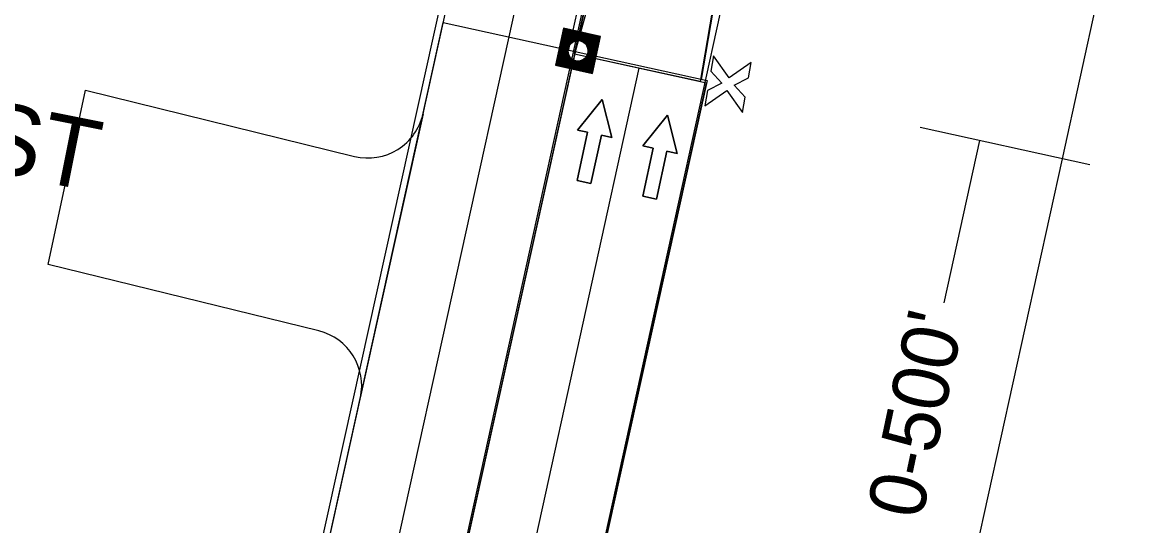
# Model space of a CAD drawing. Extents: x 14104283 to 14121738, y 8635219 to 8671666.
# Drawn here: x 14107527.6 to 14107724.8, y 8638157 to 8638246.4 of the extents above; entities that cross this region are included whole.
import ezdxf

# ---------------------------------------------------------------- set-up
doc = ezdxf.new("R2010")
doc.units = 0
for name, color, linetype in [('Cell', 7, 'Continuous'), ('Default', 7, 'Continuous'), ('dsnCellElements', 7, 'Continuous'), ('dsnNonPlotable', 7, 'Continuous'), ('dsnPaintExistingBrokenLaneLineWhite', 7, 'Continuous'), ('dsnPaintExistingDoubleCenterYellow', 7, 'Continuous'), ('dsnPaintExistingEdgeLineRightWhite', 7, 'Continuous'), ('dsnStdLabel', 7, 'Continuous'), ('dsnTapePlaceChannelizingLaneWhite', 7, 'Continuous'), ('dsnTapeRemoveChannelizingYellow', 7, 'Continuous'), ('dsnTextOverlapOdd', 7, 'Continuous')]:
    doc.layers.add(name, color=color, linetype=linetype)

msp = doc.modelspace()

# ---------------------------------------------------------------- linework, layer by layer
at = {"layer": 'Cell'}
for p, q in [((14107650.37, 8638240.4), (14107649.9, 8638237.69)), ((14107653.12, 8638236.5), (14107650.37, 8638240.4)), ((14107657.02, 8638239.24), (14107653.12, 8638236.5)), ((14107656.55, 8638236.53), (14107657.02, 8638239.24)), ((14107649.9, 8638237.69), (14107651.82, 8638235.58)), ((14107654.03, 8638235.19), (14107656.55, 8638236.53)), ((14107648.83, 8638231.54), (14107652.73, 8638234.28)), ((14107649.3, 8638234.24), (14107648.83, 8638231.54)), ((14107651.82, 8638235.58), (14107649.3, 8638234.24)), ((14107652.73, 8638234.28), (14107655.47, 8638230.37)), ((14107655.95, 8638233.08), (14107654.03, 8638235.19)), ((14107655.47, 8638230.37), (14107655.95, 8638233.08))]:
    msp.add_line(p, q, dxfattribs=at)
for points in [[(14107628.58, 8638217.76), (14107626.13, 8638218.29), (14107628, 8638226.84), (14107626.17, 8638227.24), (14107630.55, 8638232.68), (14107632.27, 8638225.91), (14107630.44, 8638226.31)], [(14107640.21, 8638214.94), (14107637.77, 8638215.47), (14107639.63, 8638224.02), (14107637.8, 8638224.42), (14107642.19, 8638229.86), (14107643.91, 8638223.09), (14107642.08, 8638223.49)]]:
    msp.add_lwpolyline(points, close=True, dxfattribs=at)
for points in [[(14107630.44, 8638226.31), (14107632.27, 8638225.91), (14107630.55, 8638232.68), (14107626.17, 8638227.24), (14107628, 8638226.84), (14107626.13, 8638218.29), (14107628.58, 8638217.76), (14107630.44, 8638226.31)], [(14107642.08, 8638223.49), (14107643.91, 8638223.09), (14107642.19, 8638229.86), (14107637.8, 8638224.42), (14107639.63, 8638224.02), (14107637.77, 8638215.47), (14107640.21, 8638214.94), (14107642.08, 8638223.49)]]:
    msp.add_lwpolyline(points, dxfattribs=at)
at = {"layer": 'Default'}
for p, q in [((14107707.57, 8638617.25), (14107624.55, 8638241.31)), ((14107625.69, 8638240.73), (14107678.16, 8638479.59)), ((14107689.3, 8638477.5), (14107647.95, 8638235.83)), ((14107647.95, 8638235.83), (14107625.69, 8638240.73)), ((14107532.18, 8638203.37), (14107538.83, 8638234.29)), ((14107538.83, 8638234.29), (14107586.62, 8638222.56)), ((14107598.77, 8638230.12), (14107587.63, 8638179.71)), ((14107580.25, 8638191.57), (14107532.18, 8638203.37))]:
    msp.add_line(p, q, dxfattribs=at)
for points in [[(14107392.92, 8637186.73), (14107369.48, 8637191.91), (14107655.09, 8638485.14), (14107678.52, 8638479.96)], [(14107602.34, 8638246.31), (14107649.23, 8638236.01), (14107496.22, 8637543.21), (14107449.34, 8637553.51)], [(14107416.35, 8637181.55), (14107649.12, 8638235.55), (14107625.69, 8638240.73), (14107392.92, 8637186.73)]]:
    msp.add_lwpolyline(points, close=True, dxfattribs=at)
for centre, start, end in [((14107589, 8638232.28), 256.2115, 347.5463), ((14107577.87, 8638181.86), 347.5463, 76.2115)]:
    msp.add_arc(centre, 10, start, end, dxfattribs=at)
at = {"layer": 'dsnCellElements'}
msp.add_circle((14107626.29, 8638241.3), 1.81, dxfattribs=at)
at = {"layer": 'dsnNonPlotable'}
for p, q in [((14107626.27, 8638241.3), (14107626.27, 8638241.3)), ((14107621.98, 8638221.77), (14107621.98, 8638221.77))]:
    msp.add_line(p, q, dxfattribs=at)
at = {"layer": 'dsnPaintExistingBrokenLaneLineWhite'}
for p, q in [((14107381.2, 8637189.32), (14107721.79, 8638731.54)), ((14107447.5, 8637375.04), (14107637.12, 8638238.2))]:
    msp.add_line(p, q, dxfattribs=at)
at = {"layer": 'dsnPaintExistingDoubleCenterYellow'}
msp.add_line((14107435.78, 8637377.61), (14107677.97, 8638480.08), dxfattribs=at)
at = {"layer": 'dsnPaintExistingEdgeLineRightWhite'}
for p, q in [((14107468.79, 8637415.99), (14107828.52, 8639053.57)), ((14107708.89, 8638734.37), (14107415.88, 8637407.61))]:
    msp.add_line(p, q, dxfattribs=at)
at = {"layer": 'dsnStdLabel'}
for p, q in [((14107712.3, 8638222.15), (14107734.73, 8638324.26)), ((14107717.18, 8638221.08), (14107687.07, 8638227.69)), ((14107691.31, 8638196.54), (14107697.65, 8638225.37)), ((14107689.02, 8638116.2), (14107712.3, 8638222.15))]:
    msp.add_line(p, q, dxfattribs=at)
for points in [[(14107628.86, 8638237.28), (14107630.31, 8638243.86), (14107623.73, 8638245.32), (14107622.28, 8638238.74), (14107628.86, 8638237.28)], [(14107628.85, 8638237.28), (14107630.31, 8638243.86), (14107623.73, 8638245.31), (14107622.28, 8638238.74), (14107628.86, 8638237.29)], [(14107628.85, 8638237.28), (14107630.3, 8638243.86), (14107623.74, 8638245.31), (14107622.29, 8638238.74), (14107628.86, 8638237.29)], [(14107628.85, 8638237.44), (14107630.26, 8638243.83), (14107623.76, 8638245.26), (14107622.33, 8638238.77), (14107628.87, 8638237.33)], [(14107628.82, 8638237.48), (14107630.21, 8638243.8), (14107623.79, 8638245.22), (14107622.37, 8638238.8), (14107628.87, 8638237.36)], [(14107628.79, 8638237.53), (14107630.17, 8638243.77), (14107623.82, 8638245.18), (14107622.42, 8638238.82), (14107628.88, 8638237.4)], [(14107628.76, 8638237.57), (14107630.13, 8638243.75), (14107623.85, 8638245.13), (14107622.46, 8638238.85), (14107628.85, 8638237.44)], [(14107628.74, 8638237.61), (14107630.08, 8638243.72), (14107623.87, 8638245.09), (14107622.5, 8638238.88), (14107628.82, 8638237.48)], [(14107628.71, 8638237.66), (14107630.04, 8638243.69), (14107623.9, 8638245.05), (14107622.55, 8638238.91), (14107628.79, 8638237.53)], [(14107628.68, 8638237.7), (14107630, 8638243.66), (14107623.93, 8638245), (14107622.59, 8638238.93), (14107628.76, 8638237.57)], [(14107628.65, 8638237.74), (14107629.95, 8638243.64), (14107623.96, 8638244.96), (14107622.63, 8638238.96), (14107628.74, 8638237.61)], [(14107628.63, 8638237.79), (14107629.91, 8638243.61), (14107623.98, 8638244.92), (14107622.67, 8638238.99), (14107628.71, 8638237.66)], [(14107628.6, 8638237.83), (14107629.87, 8638243.58), (14107624.01, 8638244.87), (14107622.72, 8638239.02), (14107628.68, 8638237.7)], [(14107628.57, 8638237.87), (14107629.82, 8638243.55), (14107624.04, 8638244.83), (14107622.76, 8638239.05), (14107628.65, 8638237.74)], [(14107628.54, 8638237.92), (14107629.78, 8638243.53), (14107624.07, 8638244.79), (14107622.8, 8638239.07), (14107628.63, 8638237.79)], [(14107628.52, 8638237.96), (14107629.74, 8638243.5), (14107624.09, 8638244.74), (14107622.85, 8638239.1), (14107628.6, 8638237.83)], [(14107628.49, 8638238), (14107629.7, 8638243.47), (14107624.12, 8638244.7), (14107622.89, 8638239.13), (14107628.57, 8638237.87)], [(14107628.46, 8638238.05), (14107629.65, 8638243.44), (14107624.15, 8638244.66), (14107622.93, 8638239.16), (14107628.54, 8638237.92)], [(14107628.43, 8638238.09), (14107629.61, 8638243.41), (14107624.18, 8638244.61), (14107622.98, 8638239.18), (14107628.52, 8638237.96)], [(14107628.4, 8638238.13), (14107629.57, 8638243.39), (14107624.21, 8638244.57), (14107623.02, 8638239.21), (14107628.49, 8638238)], [(14107628.38, 8638238.18), (14107629.52, 8638243.36), (14107624.23, 8638244.53), (14107623.06, 8638239.24), (14107628.46, 8638238.05)], [(14107628.35, 8638238.22), (14107629.48, 8638243.33), (14107624.26, 8638244.48), (14107623.11, 8638239.27), (14107628.43, 8638238.09)], [(14107628.32, 8638238.26), (14107629.44, 8638243.3), (14107624.29, 8638244.44), (14107623.15, 8638239.29), (14107628.4, 8638238.13)], [(14107628.29, 8638238.31), (14107629.39, 8638243.28), (14107624.32, 8638244.4), (14107623.19, 8638239.32), (14107628.38, 8638238.18)], [(14107628.27, 8638238.35), (14107629.35, 8638243.25), (14107624.34, 8638244.35), (14107623.24, 8638239.35), (14107628.35, 8638238.22)], [(14107628.24, 8638238.39), (14107629.31, 8638243.22), (14107624.37, 8638244.31), (14107623.28, 8638239.38), (14107628.32, 8638238.26)], [(14107628.21, 8638238.44), (14107629.26, 8638243.19), (14107624.4, 8638244.27), (14107623.32, 8638239.4), (14107628.29, 8638238.31)], [(14107628.18, 8638238.48), (14107629.22, 8638243.17), (14107624.43, 8638244.22), (14107623.37, 8638239.43), (14107628.27, 8638238.35)], [(14107628.16, 8638238.52), (14107629.18, 8638243.14), (14107624.45, 8638244.18), (14107623.41, 8638239.46), (14107628.24, 8638238.39)], [(14107628.13, 8638238.57), (14107629.13, 8638243.11), (14107624.48, 8638244.14), (14107623.45, 8638239.49), (14107628.21, 8638238.44)], [(14107628.1, 8638238.61), (14107629.09, 8638243.08), (14107624.51, 8638244.09), (14107623.5, 8638239.51), (14107628.18, 8638238.48)], [(14107628.07, 8638238.65), (14107629.05, 8638243.06), (14107624.54, 8638244.05), (14107623.54, 8638239.54), (14107628.16, 8638238.52)], [(14107628.05, 8638238.7), (14107629, 8638243.03), (14107624.56, 8638244.01), (14107623.58, 8638239.57), (14107628.13, 8638238.57)], [(14107628.02, 8638238.74), (14107628.96, 8638243), (14107624.59, 8638243.97), (14107623.63, 8638239.6), (14107628.1, 8638238.61)], [(14107627.99, 8638238.78), (14107628.92, 8638242.97), (14107624.62, 8638243.92), (14107623.67, 8638239.62), (14107628.07, 8638238.65)], [(14107627.96, 8638238.83), (14107628.87, 8638242.95), (14107624.65, 8638243.88), (14107623.71, 8638239.65), (14107628.05, 8638238.7)], [(14107627.94, 8638238.87), (14107628.83, 8638242.92), (14107624.67, 8638243.84), (14107623.76, 8638239.68), (14107628.02, 8638238.74)], [(14107627.91, 8638238.91), (14107628.79, 8638242.89), (14107624.7, 8638243.79), (14107623.8, 8638239.71), (14107627.99, 8638238.78)], [(14107627.88, 8638238.96), (14107628.74, 8638242.86), (14107624.73, 8638243.75), (14107623.84, 8638239.74), (14107627.96, 8638238.83)], [(14107627.85, 8638239), (14107628.7, 8638242.83), (14107624.76, 8638243.71), (14107623.89, 8638239.76), (14107627.94, 8638238.87)], [(14107627.82, 8638239.04), (14107628.66, 8638242.81), (14107624.78, 8638243.66), (14107623.93, 8638239.79), (14107627.91, 8638238.91)], [(14107627.8, 8638239.09), (14107628.61, 8638242.78), (14107624.81, 8638243.62), (14107623.97, 8638239.82), (14107627.88, 8638238.96)], [(14107627.77, 8638239.13), (14107628.57, 8638242.75), (14107624.84, 8638243.58), (14107624.02, 8638239.85), (14107627.85, 8638239)], [(14107627.74, 8638239.17), (14107628.53, 8638242.72), (14107624.87, 8638243.53), (14107624.06, 8638239.87), (14107627.82, 8638239.04)], [(14107627.71, 8638239.22), (14107628.48, 8638242.7), (14107624.9, 8638243.49), (14107624.1, 8638239.9), (14107627.8, 8638239.09)], [(14107627.69, 8638239.26), (14107628.44, 8638242.67), (14107624.92, 8638243.45), (14107624.15, 8638239.93), (14107627.77, 8638239.13)], [(14107626.34, 8638243.1), (14107624.95, 8638243.4), (14107624.64, 8638242.01)], [(14107626.19, 8638243.09), (14107624.98, 8638243.36), (14107624.71, 8638242.15)], [(14107626.07, 8638243.08), (14107625.01, 8638243.32), (14107624.77, 8638242.25)], [(14107625.97, 8638243.07), (14107625.03, 8638243.27), (14107624.83, 8638242.34)], [(14107625.88, 8638243.05), (14107625.06, 8638243.23), (14107624.88, 8638242.41)], [(14107625.8, 8638243.03), (14107625.09, 8638243.19), (14107624.93, 8638242.47)], [(14107625.73, 8638243.01), (14107625.12, 8638243.14), (14107624.98, 8638242.53)], [(14107625.67, 8638242.98), (14107625.14, 8638243.1), (14107625.03, 8638242.57)], [(14107625.61, 8638242.96), (14107625.17, 8638243.06), (14107625.08, 8638242.62)], [(14107625.55, 8638242.94), (14107625.2, 8638243.01), (14107625.12, 8638242.66)], [(14107625.5, 8638242.91), (14107625.23, 8638242.97), (14107625.17, 8638242.7)], [(14107625.45, 8638242.88), (14107625.25, 8638242.93), (14107625.21, 8638242.73)], [(14107625.4, 8638242.86), (14107625.28, 8638242.88), (14107625.26, 8638242.77)], [(14107625.35, 8638242.83), (14107625.31, 8638242.84), (14107625.3, 8638242.8)], [(14107628.09, 8638241.25), (14107628.4, 8638242.64), (14107627, 8638242.95)], [(14107628.09, 8638241.41), (14107628.35, 8638242.61), (14107627.15, 8638242.88)], [(14107628.08, 8638241.52), (14107628.31, 8638242.59), (14107627.25, 8638242.82)], [(14107628.06, 8638241.62), (14107628.27, 8638242.56), (14107627.33, 8638242.77)], [(14107628.04, 8638241.71), (14107628.22, 8638242.53), (14107627.4, 8638242.71)], [(14107628.02, 8638241.79), (14107628.18, 8638242.5), (14107627.46, 8638242.66)], [(14107628, 8638241.86), (14107628.14, 8638242.48), (14107627.52, 8638242.61)], [(14107627.98, 8638241.92), (14107628.09, 8638242.45), (14107627.57, 8638242.56)], [(14107627.95, 8638241.98), (14107628.05, 8638242.42), (14107627.61, 8638242.52)], [(14107627.93, 8638242.04), (14107628.01, 8638242.39), (14107627.66, 8638242.47)], [(14107627.9, 8638242.09), (14107627.96, 8638242.37), (14107627.69, 8638242.43)], [(14107627.88, 8638242.15), (14107627.92, 8638242.34), (14107627.73, 8638242.38)], [(14107627.85, 8638242.19), (14107627.88, 8638242.31), (14107627.76, 8638242.34)], [(14107627.82, 8638242.24), (14107627.83, 8638242.28), (14107627.79, 8638242.29)], [(14107624.5, 8638241.35), (14107624.19, 8638239.96), (14107625.58, 8638239.65)], [(14107624.5, 8638241.19), (14107624.23, 8638239.98), (14107625.44, 8638239.72)], [(14107624.51, 8638241.07), (14107624.28, 8638240.01), (14107625.34, 8638239.78)], [(14107624.53, 8638240.97), (14107624.32, 8638240.04), (14107625.25, 8638239.83)], [(14107624.54, 8638240.89), (14107624.36, 8638240.07), (14107625.18, 8638239.89)], [(14107624.56, 8638240.81), (14107624.41, 8638240.09), (14107625.12, 8638239.94)], [(14107624.59, 8638240.74), (14107624.45, 8638240.12), (14107625.07, 8638239.99)], [(14107624.61, 8638240.67), (14107624.49, 8638240.15), (14107625.02, 8638240.03)], [(14107624.63, 8638240.61), (14107624.54, 8638240.18), (14107624.97, 8638240.08)], [(14107624.66, 8638240.56), (14107624.58, 8638240.2), (14107624.93, 8638240.13)], [(14107624.68, 8638240.5), (14107624.62, 8638240.23), (14107624.89, 8638240.17)], [(14107624.71, 8638240.45), (14107624.67, 8638240.26), (14107624.86, 8638240.22)], [(14107624.73, 8638240.4), (14107624.71, 8638240.29), (14107624.83, 8638240.26)], [(14107624.76, 8638240.36), (14107624.75, 8638240.32), (14107624.8, 8638240.31)], [(14107627.49, 8638239.56), (14107627.61, 8638240.07)], [(14107627.52, 8638239.52), (14107627.66, 8638240.13)], [(14107627.55, 8638239.47), (14107627.71, 8638240.19)], [(14107627.58, 8638239.43), (14107627.76, 8638240.26)], [(14107627.6, 8638239.39), (14107627.82, 8638240.34)], [(14107627.63, 8638239.34), (14107627.87, 8638240.45)], [(14107627.66, 8638239.3), (14107627.94, 8638240.59)], [(14107626.24, 8638239.5), (14107627.74, 8638239.17)], [(14107626.4, 8638239.51), (14107627.71, 8638239.22)], [(14107626.52, 8638239.52), (14107627.69, 8638239.26)], [(14107626.62, 8638239.53), (14107627.66, 8638239.3)], [(14107626.7, 8638239.55), (14107627.63, 8638239.34)], [(14107626.78, 8638239.57), (14107627.6, 8638239.39)], [(14107626.85, 8638239.59), (14107627.58, 8638239.43)], [(14107626.92, 8638239.61), (14107627.55, 8638239.47)], [(14107626.98, 8638239.64), (14107627.52, 8638239.52)], [(14107627.04, 8638239.66), (14107627.49, 8638239.56)], [(14107627.09, 8638239.69), (14107627.47, 8638239.6)], [(14107627.14, 8638239.71), (14107627.44, 8638239.65)], [(14107627.19, 8638239.74), (14107627.41, 8638239.69)], [(14107627.23, 8638239.77), (14107627.38, 8638239.73)], [(14107627.38, 8638239.73), (14107627.42, 8638239.9)], [(14107627.41, 8638239.69), (14107627.46, 8638239.94)], [(14107627.44, 8638239.65), (14107627.51, 8638239.98)], [(14107627.47, 8638239.6), (14107627.56, 8638240.02)]]:
    msp.add_lwpolyline(points, dxfattribs=at)
at = {"layer": 'dsnTapePlaceChannelizingLaneWhite'}
msp.add_line((14107648.21, 8638236.23), (14107689.3, 8638477.5), dxfattribs=at)
at = {"layer": 'dsnTapeRemoveChannelizingYellow'}
msp.add_line((14107690.68, 8638477.29), (14107625.69, 8638240.73), dxfattribs=at)

# ---------------------------------------------------------------- texts
at = {"layer": 'dsnStdLabel'}
msp.add_text("0-500'", height=10, rotation=78.0531, dxfattribs=at).set_placement((14107687.3, 8638157.84))
at = {"layer": 'dsnTextOverlapOdd'}
msp.add_text('MAPLE ST', height=12.5, rotation=348.6912, dxfattribs=at).set_placement((14107458.91, 8638232.49))

doc.saveas('drawing.dxf')
